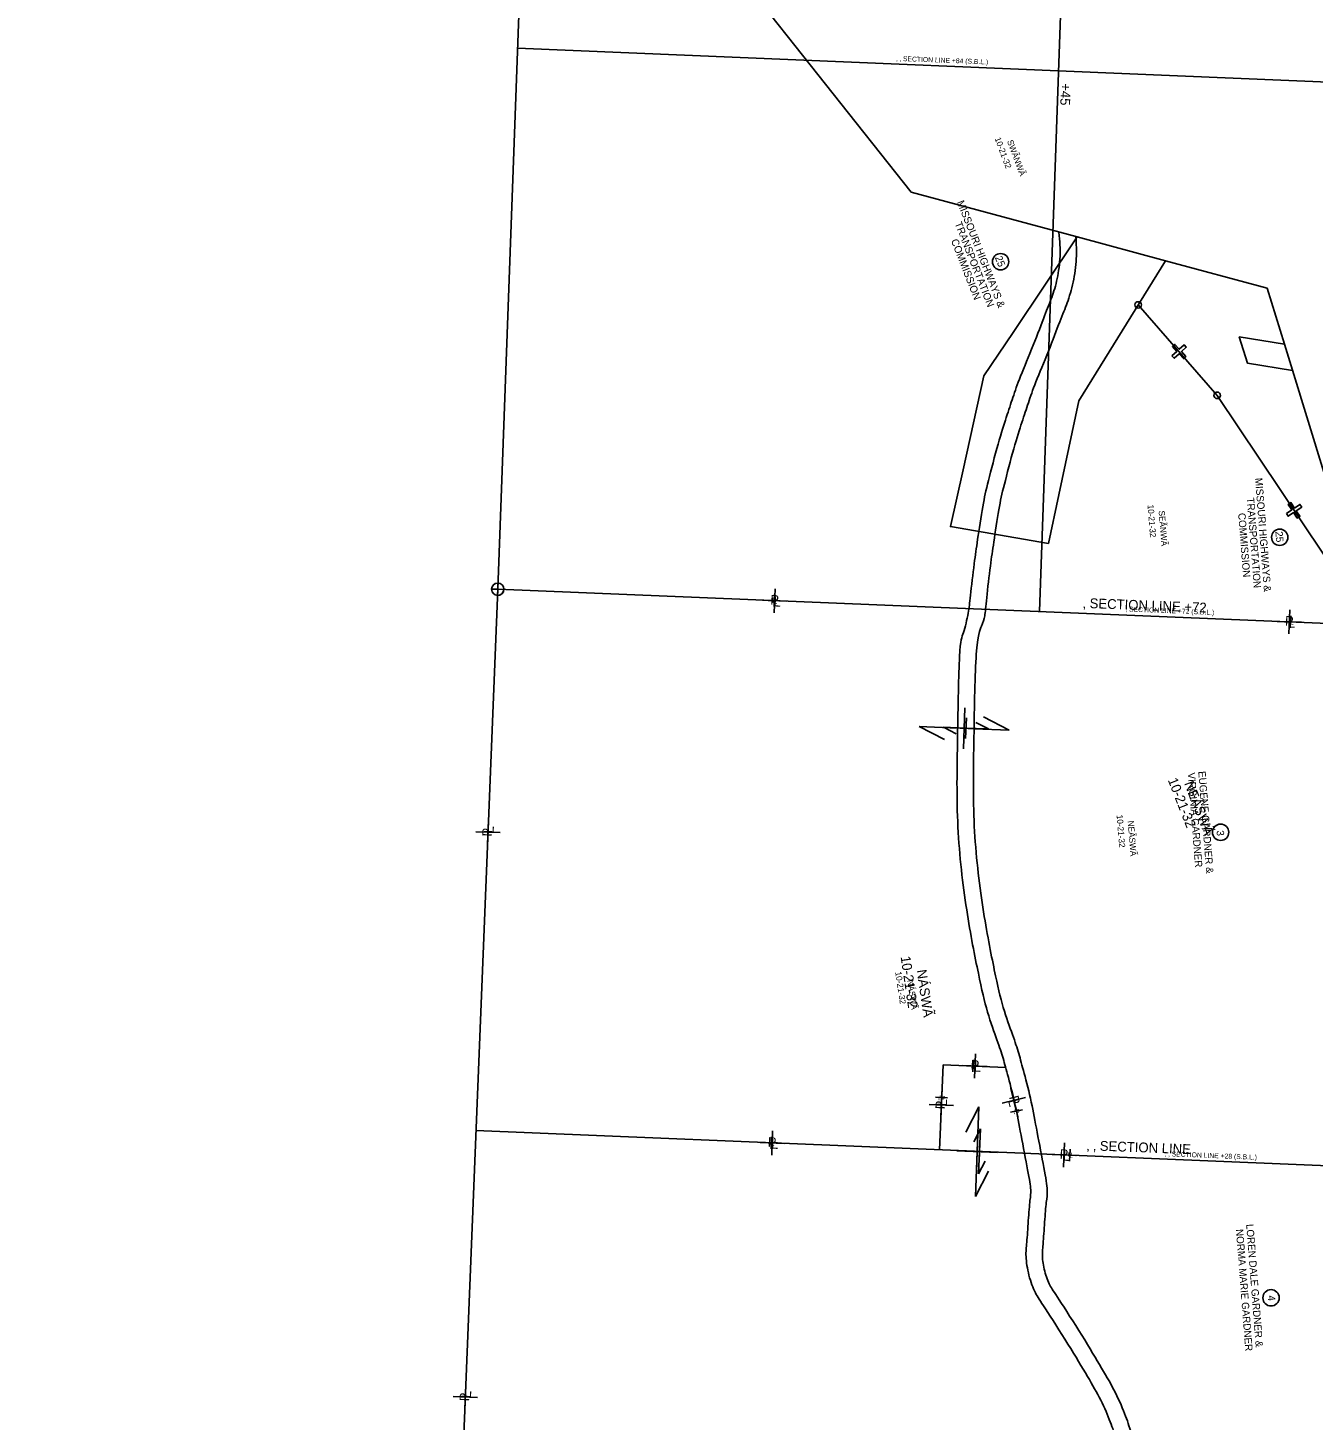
# Model space of a CAD drawing. Extents: x 2814293 to 2835768, y 121185 to 156337.
# Drawn here: x 2820000 to 2823143, y 142248 to 145654 of the extents above; entities that cross this region are included whole.
import ezdxf

# ---------------------------------------------------------------- set-up
doc = ezdxf.new("R2010")
doc.units = 0
for name, color, linetype in [('Default', 7, 'Continuous'), ('Photo-Retaining wall', 7, 'Continuous'), ('Roadway-Alignment notes', 7, 'Continuous'), ('Roadway-Ditches', 7, 'Continuous'), ('Roadway-Edge of pavement', 7, 'Continuous'), ('Roadway-Edge of shoulder', 7, 'Continuous'), ('Roadway-Entrances', 7, 'Continuous'), ('Roadway-New rw', 7, 'Continuous'), ('Roadway-Safety', 7, 'Continuous'), ('Roadway-Walls', 7, 'Continuous'), ('Scratch-2', 7, 'Continuous'), ('Scratch-4', 7, 'Continuous'), ('Scratch-5', 7, 'Continuous'), ('Text-New rw label', 7, 'Continuous'), ('Traffic_Control-Traffic barriers', 7, 'Continuous')]:
    doc.layers.add(name, color=color, linetype=linetype)

msp = doc.modelspace()

# ---------------------------------------------------------------- linework, layer by layer
at = {"layer": 'Default'}
for p, q in [((2822291.4, 143990.5), (2822287.5, 143890.6)), ((2822295, 143966), (2822293, 143916)), ((2822239.5, 143942.5), (2822339.4, 143938.6)), ((2822269, 143942), (2822319, 143940.1))]:
    msp.add_line(p, q, dxfattribs=at)
at = {"layer": 'Roadway-Ditches'}
for centre in [(2822378.5, 145081.9), (2823061.1, 144407.8), (2822916.6, 143686.3), (2823039.9, 142547.6)]:
    msp.add_circle(centre, 20, dxfattribs=at)
at = {"layer": 'Roadway-Edge of pavement'}
for p, q in [((2822317.8, 143954.9), (2822348.9, 143938.9)), ((2822270.1, 143927.1), (2822239, 143943.2)), ((2822273.7, 143941.8), (2822239, 143943.2)), ((2822294, 143941), (2822294, 143941)), ((2822348.9, 143938.9), (2822313.7, 143940.3)), ((2822313.2, 142929.5), (2822329.2, 142960.6)), ((2822329.2, 142960.6), (2822324.9, 142850.7)), ((2822326.1, 142880.6), (2822328, 142930.6)), ((2822302.1, 142906.6), (2822352, 142904.7)), ((2822327, 142905.6), (2822327, 142905.6)), ((2822340.9, 142881.8), (2822324.9, 142850.7))]:
    msp.add_line(p, q, dxfattribs=at)
at = {"layer": 'Roadway-Edge of shoulder'}
for p, q in [((2821827.3, 144282), (2821825, 144223.2)), ((2821796.7, 144253.8), (2821855.6, 144251.5)), ((2823085.8, 144230.4), (2823083.6, 144171.5)), ((2823055.3, 144202.1), (2823114.1, 144199.8)), ((2821123.8, 143657.1), (2821126.1, 143716)), ((2821095.5, 143687.7), (2821154.4, 143685.4)), ((2822317.2, 143144.1), (2822314.9, 143085.2)), ((2822286.6, 143115.8), (2822345.5, 143113.5)), ((2822232.4, 142989.9), (2822234.7, 143048.8)), ((2822439.4, 143037.9), (2822382.2, 143023.9)), ((2822403.8, 143059.5), (2822417.8, 143002.3)), ((2822204.1, 143020.5), (2822263, 143018.2)), ((2821790.5, 142927.4), (2821849.4, 142925.1)), ((2821821.1, 142955.7), (2821818.8, 142896.8)), ((2822504.3, 142898), (2822563.2, 142895.7)), ((2822534.9, 142926.3), (2822532.6, 142867.4)), ((2821068.4, 142275.8), (2821070.7, 142334.7)), ((2821040.1, 142306.4), (2821099, 142304.1))]:
    msp.add_line(p, q, dxfattribs=at)
at = {"layer": 'Roadway-Entrances'}
for p, q in [((2821245.6, 146923.2), (2821148.7, 144280.6)), ((2822566.2, 146867.7), (2822473.6, 144225.9)), ((2821197.2, 145604), (2823831.6, 145493.6)), ((2821042.3, 141632.4), (2821148.7, 144280.6)), ((2821148.7, 144280.6), (2823284.2, 144192.5)), ((2821095.2, 142957.1), (2823750.2, 142846.3))]:
    msp.add_line(p, q, dxfattribs=at)
at = {"layer": 'Roadway-New rw'}
for p, q in [((2822714.8, 144976.1), (2822908.4, 144755)), ((2822908.4, 144755), (2823284.2, 144192.5))]:
    msp.add_line(p, q, dxfattribs=at)
for points in [[(2822797.7, 144851.6), (2822803.1, 144845.7), (2822815, 144856.5), (2822825.7, 144844.7), (2822831.7, 144850.1), (2822820.9, 144861.9), (2822832.7, 144872.7), (2822827.3, 144878.6), (2822815.5, 144867.8), (2822804.7, 144879.6), (2822798.8, 144874.2), (2822809.6, 144862.4), (2822797.7, 144851.6)], [(2823077.5, 144466), (2823081.9, 144459.3), (2823095.2, 144468.2), (2823104.1, 144454.9), (2823110.7, 144459.3), (2823101.8, 144472.6), (2823115.2, 144481.5), (2823110.7, 144488.2), (2823097.4, 144479.3), (2823088.5, 144492.6), (2823081.9, 144488.1), (2823090.8, 144474.8), (2823077.5, 144466)]]:
    msp.add_lwpolyline(points, close=True, dxfattribs=at)
at = {"layer": 'Roadway-Walls'}
for p, q in [((2821825.8, 144267.6), (2821824.6, 144238.2)), ((2821810.5, 144253.5), (2821839.9, 144252.3)), ((2823072.9, 144201.4), (2823102.3, 144200.2)), ((2823088.2, 144215.5), (2823087, 144186.1)), ((2822296.8, 143115.3), (2822326.2, 143114.1)), ((2822312.1, 143129.4), (2822311, 143100)), ((2822249.1, 143037.1), (2822219.7, 143038.2)), ((2822235, 143052.3), (2822233.8, 143022.9)), ((2822431.9, 143007.5), (2822403, 143001.5)), ((2822414.4, 143018.9), (2822420.4, 142990)), ((2821803.2, 142927.6), (2821832.6, 142926.4)), ((2821818.5, 142941.7), (2821817.3, 142912.3)), ((2822533.3, 142897.1), (2822562.7, 142896)), ((2822548.6, 142911.2), (2822547.4, 142881.8))]:
    msp.add_line(p, q, dxfattribs=at)
at = {"layer": 'Scratch-2'}
for p, q in [((2822337.1, 143968.3), (2822399.3, 143936.3)), ((2822241.8, 143912.8), (2822179.5, 143944.8)), ((2822273.7, 143941.2), (2822179.5, 143944.8)), ((2822289.4, 143940.6), (2822289.4, 143940.6)), ((2822399.3, 143936.3), (2822313.6, 143939.6)), ((2822293.6, 142952.7), (2822325.6, 143015)), ((2822325.6, 143015), (2822317.1, 142795.1)), ((2822319.4, 142855.1), (2822323.3, 142955)), ((2822271.4, 142907), (2822371.3, 142903.1)), ((2822321.3, 142905.1), (2822321.3, 142905.1)), ((2822349.1, 142857.4), (2822317.1, 142795.1))]:
    msp.add_line(p, q, dxfattribs=at)
at = {"layer": 'Scratch-4'}
for p, q in [((2821148.7, 144280.6), (2821149.2, 144295.6)), ((2821133.7, 144281.1), (2821148.7, 144280.6)), ((2821148.7, 144280.6), (2821148.2, 144265.6)), ((2821163.7, 144280.1), (2821148.7, 144280.6))]:
    msp.add_line(p, q, dxfattribs=at)
msp.add_circle((2821148.7, 144280.6), 15, dxfattribs=at)
for start, end in [(88.1, 178.1), (268.1, 358.1)]:
    msp.add_arc((2821148.7, 144280.6), 15, start, end, dxfattribs=at)
at = {"layer": 'Text-New rw label'}
for centre in [(2822714.8, 144976.1), (2822908.4, 144755)]:
    msp.add_circle(centre, 8, dxfattribs=at)
at = {"layer": 'Traffic_Control-Traffic barriers'}
for p, q in [((2822237.9, 143117.6), (2822229.2, 142909.8)), ((2822390.9, 143111.2), (2822237.9, 143117.6))]:
    msp.add_line(p, q, dxfattribs=at)
for points in [[(2819850.1, 149939.6), (2820531.6, 149276.8), (2821431.4, 147698.1), (2821413.4, 147540.2), (2821396.7, 147393.2), (2821369.3, 147151.1), (2821340.3, 146896.2), (2821740.6, 145780.7), (2822160.2, 145252), (2822565.5, 145142.6), (2822781.5, 145084.2), (2823030.3, 145017.1), (2823072.5, 144880), (2823092.1, 144816.2), (2823284.2, 144192.5)], [(2822565.5, 145142.6), (2822409.2, 144908.9), (2822337.9, 144802.3), (2822287, 144573.1), (2822256, 144434), (2822495.4, 144393), (2822520.9, 144511.7), (2822570.3, 144741.8), (2822781.5, 145084.2)], [(2823072.5, 144880), (2822962.4, 144898), (2822982, 144834), (2823092.2, 144816)]]:
    msp.add_lwpolyline(points, dxfattribs=at)
for points in [[(2822619.1, 138791.9), (2822623.3, 138830.4), (2822627.9, 138868.3), (2822646.1, 138913.9), (2822679.5, 138992.1), (2822698.2, 139038.1), (2822719.4, 139101.6), (2822737.2, 139223.3), (2822763.5, 139483.6), (2822768.3, 139574.7), (2822769.1, 139633.3), (2822771.8, 139741.2), (2822766.3, 139803.1), (2822752.2, 139846.7), (2822732.7, 139917), (2822721, 139977.9), (2822710.3, 140035.7), (2822699.8, 140123), (2822697.3, 140218.9), (2822694.4, 140324.5), (2822689.5, 140431.6), (2822690.1, 140547.7), (2822693.6, 140672.5), (2822702.4, 140829), (2822715.6, 140985.8), (2822740.8, 141221.6), (2822751.4, 141457.2), (2822753.3, 141653.7), (2822748.8, 141833.4), (2822745, 141874), (2822737.3, 141918.3), (2822713.5, 142020.4), (2822693.8, 142083.7), (2822659.6, 142205.9), (2822649.1, 142240.5), (2822624.5, 142298.2), (2822593.7, 142351.1), (2822546.4, 142430.7), (2822480.1, 142534), (2822463.8, 142556.3), (2822446.4, 142602), (2822438.8, 142652.6), (2822442.7, 142678), (2822446.2, 142737), (2822450.6, 142792.4), (2822454, 142807.1), (2822446.8, 142851.5), (2822427.2, 142951.1), (2822416.1, 143016.1), (2822396, 143092), (2822385, 143134), (2822371.9, 143173.6), (2822345.3, 143244.4), (2822326.3, 143328.8), (2822294.5, 143488.6), (2822269.4, 143698.3), (2822273.3, 143914), (2822277.1, 144153.7), (2822287.1, 144167.5), (2822301.3, 144227.5), (2822303.2, 144254.3), (2822314.9, 144351.8), (2822321.1, 144393.5), (2822335.7, 144491.2), (2822346, 144536.6), (2822373.7, 144643.1), (2822393.2, 144703.5), (2822408.7, 144750), (2822424.4, 144796.1), (2822459.5, 144878.5), (2822488.1, 144956.1), (2822504, 144993.2), (2822518.1, 145038.9), (2822525.7, 145096), (2822523.6, 145130.9), (2822521.2, 145154.4)], [(2822658.9, 138787.6), (2822663, 138825.8), (2822667, 138858.3), (2822683.1, 138898.6), (2822716.4, 138976.7), (2822735.8, 139024.2), (2822758.5, 139092.3), (2822776.9, 139218.4), (2822803.4, 139480.5), (2822808.3, 139573.4), (2822809.1, 139632.5), (2822811.8, 139742.5), (2822805.8, 139811.1), (2822790.5, 139858.2), (2822771.7, 139926.1), (2822760.3, 139985.4), (2822749.8, 140041.7), (2822739.7, 140125.9), (2822737.3, 140219.9), (2822734.4, 140325.9), (2822729.5, 140432.4), (2822730.1, 140547), (2822733.6, 140670.8), (2822742.3, 140826.2), (2822755.4, 140982), (2822780.7, 141218.6), (2822791.4, 141456.1), (2822793.3, 141654), (2822788.7, 141835.7), (2822784.7, 141879.2), (2822776.6, 141926.3), (2822752.1, 142030.9), (2822732.2, 142095), (2822698, 142217.1), (2822686.7, 142254.1), (2822660.3, 142316.2), (2822628.2, 142371.4), (2822580.4, 142451.8), (2822513.1, 142556.7), (2822499.3, 142575.6), (2822485.3, 142612.2), (2822479.2, 142652.5), (2822482.5, 142673.7), (2822486.1, 142734.2), (2822490.3, 142786.3), (2822494.7, 142805.8), (2822486.2, 142858.5), (2822466.5, 142958.3), (2822455.3, 143024.6), (2822434.7, 143102.2), (2822423.4, 143145.3), (2822409.7, 143187), (2822383.7, 143255.9), (2822365.4, 143337), (2822334.1, 143494.9), (2822309.5, 143700.3), (2822313.3, 143913.3), (2822317.1, 144155.8), (2822333.6, 144194), (2822340.3, 144212.2), (2822343.1, 144250.5), (2822354.6, 144346.5), (2822360.7, 144387.6), (2822375, 144483.8), (2822384.9, 144527.1), (2822412.2, 144631.9), (2822431.2, 144691), (2822446.6, 144737.2), (2822461.8, 144781.8), (2822496.7, 144863.7), (2822525.3, 144941.3), (2822541.6, 144979.4), (2822557.3, 145030.3), (2822565.3, 145090.5), (2822563.9, 145125.3), (2822562.5, 145142.8)]]:
    msp.add_open_spline(points, degree=3, dxfattribs=at)

# ---------------------------------------------------------------- texts
at = {"layer": 'Photo-Retaining wall'}
for s, rotation, p in [('10-21-32', 290.3561, (2822363.9, 145383.2)), ('SWÃNWÃ', 290.3561, (2822394.1, 145376.7)), ('10-21-32', 274.4738, (2822737.9, 144487)), ('SEÃNWÃ', 274.4738, (2822765.1, 144472.5)), ('10-21-32', 274.4738, (2822662.3, 143728.5)), ('NEÃSWÃ', 274.4738, (2822689.5, 143714)), ('10-21-32', 278.3561, (2822120.9, 143344.4)), ('NÁSWÃ', 278.3561, (2822150.1, 143324.3))]:
    msp.add_text(s, height=15, rotation=rotation, dxfattribs=at).set_placement(p)
at = {"layer": 'Roadway-Alignment notes'}
for s, rotation, p in [('10-21-32', 291.4209, (2822787.2, 143814.2)), ('NEÃSWÃ', 291.4209, (2822827, 143805.8)), ('10-21-32', 278.3561, (2822134, 143382)), ('NÁSWÃ', 278.3561, (2822173.3, 143348.8))]:
    msp.add_text(s, height=24, rotation=rotation, dxfattribs=at).set_placement(p)
at = {"layer": 'Roadway-Ditches'}
for s, rotation, p in [('MISSOURI HIGHWAYS &', 291.4148, (2822271.5, 145227.6)), ('TRANSPORTATION', 291.4148, (2822266.1, 145175.6)), ('COMMISSION', 291.4148, (2822256.9, 145133.4)), ('25', 291.4148, (2822364.3, 145092.2)), ('MISSOURI HIGHWAYS &', 274.4738, (2823000.8, 144552.5)), ('TRANSPORTATION', 274.4738, (2822980.5, 144504.3)), ('COMMISSION', 274.4738, (2822959.4, 144466.6)), ('25', 274.4738, (2823050.6, 144421.7)), ('VIRGINIA GARDNER', 274.4738, (2822836.2, 143831.7)), ('EUGENE GARDNER &', 274.4738, (2822862, 143835.2)), ('3', 274.4738, (2822906.7, 143690.2)), ('LOREN DALE GARDNER &', 274.4738, (2822979.1, 142727.5)), ('NORMA MARIE GARDNER', 274.4738, (2822953.9, 142715.1)), ('4', 274.4738, (2823031.8, 142552.9))]:
    msp.add_text(s, height=18, rotation=rotation, dxfattribs=at).set_placement(p)
at = {"layer": 'Roadway-Edge of shoulder'}
for s, rotation, p in [('P', 357.7804, (2821815.1, 144243.4)), ('L', 357.7804, (2821823, 144238.8)), ('P', 357.7804, (2823073.7, 144191.7)), ('L', 357.7804, (2823081.5, 144187.1)), ('P', 87.7804, (2821134.2, 143675.5)), ('L', 87.7804, (2821138.8, 143683.3)), ('P', 357.7804, (2822305, 143105.5)), ('L', 357.7804, (2822312.8, 143100.9)), ('L', 87.7804, (2822247.3, 143016.1)), ('L', 283.7804, (2822396.6, 143030.2)), ('P', 283.7804, (2822398.9, 143039)), ('P', 87.7804, (2822242.7, 143008.3)), ('P', 357.7804, (2821808.9, 142917.1)), ('L', 357.7804, (2821816.8, 142912.5)), ('P', 357.7804, (2822522.7, 142887.6)), ('L', 357.7804, (2822530.5, 142883)), ('P', 87.7804, (2821078.8, 142294.2)), ('L', 87.7804, (2821083.4, 142302))]:
    msp.add_text(s, height=23.6, rotation=rotation, dxfattribs=at).set_placement(p)
at = {"layer": 'Roadway-Safety'}
for s, p in [('‚ ‚ SECTION LINE +84 (S.B.L.)', (2822123.1, 145573.1)), ('‚ SECTION LINE +72 (S.B.L.)', (2822684.2, 144226.4)), ('‚ ‚ SECTION LINE +28 (S.B.L.)', (2822780.3, 142894.1))]:
    msp.add_text(s, height=12, rotation=357.7804, dxfattribs=at).set_placement(p)
at = {"layer": 'Roadway-Walls'}
for s, rotation, p in [('P', 357.7804, (2821819.7, 144248.3)), ('L', 357.7804, (2821823.6, 144246)), ('P', 357.7804, (2823082.1, 144196.2)), ('L', 357.7804, (2823086, 144193.9)), ('P', 357.7804, (2822306, 143110.1)), ('L', 357.7804, (2822309.9, 143107.8)), ('L', 267.7804, (2822227.5, 143039.2)), ('P', 267.7804, (2822229.8, 143043.2)), ('L', 281.7804, (2822410.3, 143004.4)), ('P', 281.7804, (2822411.6, 143008.7)), ('P', 357.7804, (2821812.4, 142922.4)), ('L', 357.7804, (2821816.3, 142920.1)), ('P', 357.7804, (2822542.5, 142891.9)), ('L', 357.7804, (2822546.4, 142889.6))]:
    msp.add_text(s, height=11.8, rotation=rotation, dxfattribs=at).set_placement(p)
at = {"layer": 'Scratch-5'}
for s, rotation, p in [('+45', 267.9924, (2822526.2, 145518.8)), ('‚ SECTION LINE +72', 357.7804, (2822579.9, 144235.3)), ('‚ ‚ SECTION LINE', 357.7804, (2822588.7, 142908.8))]:
    msp.add_text(s, height=24, rotation=rotation, dxfattribs=at).set_placement(p)

doc.saveas('drawing.dxf')
